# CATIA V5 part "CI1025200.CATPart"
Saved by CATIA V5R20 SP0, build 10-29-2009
Part number: CI1025200
Bounding box of the stored display mesh (mm): x -24 to 24, y -20.11 to 234.5, z -26.352 to 28.386
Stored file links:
  C:\Users\Raffaele\Desktop\3D X SITO CF\BOLEX\19-INCLINED ASSEMBLY REF_CI\CI1025200.CATPart
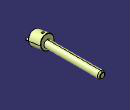
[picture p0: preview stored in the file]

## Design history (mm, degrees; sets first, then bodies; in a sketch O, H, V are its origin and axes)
Set1
  DatumSurface1 to DatumSurface16 "MANIFOLD_SOLID_BREP #393"
  DatumSurface17 to DatumSurface39 "MANIFOLD_SOLID_BREP #1138"
Body1 (main body)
